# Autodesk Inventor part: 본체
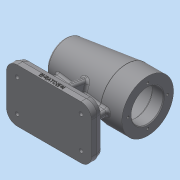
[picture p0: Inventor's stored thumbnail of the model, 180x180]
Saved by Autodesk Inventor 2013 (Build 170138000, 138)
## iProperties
Created: 2017-01
Part Number: 본체
Material: 일반
Document SubType Name: Modeling
Designer: dgall
Density: 1 g/cm^3
Author: dgall
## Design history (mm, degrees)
sketch "스케치1"
  geometry: L1 (-56, 0)-(56, 0); L2 (-52.27, 24.144)-(28, 34); L3 (28, 34)-(56, 34); L4 (56, 34)-(56, 0); L5 (-56, -60)-(56, -60); L6 (56, -60)-(56, -67); L7 (56, -67)-(-56, -67); L8 (-56, -67)-(-56, -60); L9 (-50, 0)-(-50, 10.5); L10 (-50, 10.5)-(-47, 10.5); L11 (-47, 10.5)-(-47, 16); L12 (-47, 16)-(-43, 16); L13 (-43, 16)-(-43, 17.5); L14 (-43, 17.5)-(-25, 17.5); L15 (-25, 17.5)-(-25, 21); L16 (-25, 21)-(-13, 21); L17 (-13, 21)-(-13, 24); L18 (-13, 24)-(41, 24); L19 (41, 24)-(41, 21); L20 (41, 21)-(56, 21); A1 r 80 centre (24, 0) between (-52.27, 24.144) and (-56, 0); 3 further points
  constraints: 40 end point, 14 parallel, 3 midpoint, 3 perpendicular, 2 horizontal, 2 point on circle, 2 point on line, 1 centre point, 1 coincident, 1 horizontal alignment, 1 vertical alignment
  dimensions: "d0" = 112 distance of L1.start L1.end; "d2" = 28 distance of L2.end L3.end; "d3" = 7 deg angle of L2 L3; "d4" = 80 radius of A1; "d5" = 68 diameter of L3 L1; "d6" = 7 distance of L5.end L6.end; "d7" = 67 distance from line of L1.start L7; "d8" = 112 distance of L6.end L7.end; "d9" = 15 distance of L19.end L20.end; "d10" = 54 distance of L17.end L18.end; "d11" = 12 distance of L15.end L16.end; "d12" = 18 distance of L13.end L14.end; "d13" = 4 distance of L11.end L12.end; "d14" = 3 distance of L9.end L10.end; "d15" = 21 diameter of L10 L1; "d16" = 32 diameter of L12 L1; "d17" = 35 diameter of L14 L1; "d18" = 42 diameter of L16 L1; "d19" = 48 diameter of L18 L1; "d20" = 42 diameter of L20 L1
revolve "회전1" stored, may be unused: angle "d21" = 90 deg
extrude "돌출1" join sketch "스케치1" stored distance "d22" = 70; taper "d23" = 0 deg
feature "면 기울기1" dims angle "d24" = -15 deg
fillet "모깎기1" dims "d44" = 14
sketch "스케치2"
  geometry: L1 (112, 0)-(112, -70) reference; L2 (0, 0)-(112, 0) reference; L3 (0, 0)-(0, -70) reference; L4 (112, -70)-(0, -70) reference; 1 further point
extrude "돌출2" join sketch "스케치2" distance "d25" = 7; taper "d26" = 0 deg
sketch "스케치3"
  geometry: L1 (0, 66.249)-(108.249, 66.249) reference; L2 (16.124, 37.124)-(50.124, 37.124); L3 (50.124, 37.124)-(50.124, 56.124); L4 (50.124, 56.124)-(58.124, 56.124); L5 (58.124, 56.124)-(58.124, 37.124); L6 (58.124, 37.124)-(92.124, 37.124); L7 (92.124, 37.124)-(92.124, 29.124); L8 (92.124, 29.124)-(58.124, 29.124); L9 (58.124, 29.124)-(58.124, 10.124); L10 (58.124, 10.124)-(50.124, 10.124); L11 (50.124, 10.124)-(50.124, 29.124); L12 (50.124, 29.124)-(16.124, 29.124); L13 (16.124, 29.124)-(16.124, 37.124); L14 (-1.876, 11.647)-(-1.876, 54.601) reference; L15 (96.601, 68.124)-(11.647, 68.124) reference; 6 further points
  constraints: 24 end point, 8 parallel, 3 equal length, 3 horizontal alignment, 3 vertical alignment, 2 collinear, 2 midpoint, 2 perpendicular
  dimensions: "d27" = 8 distance of L3.end L4.end; "d29" = 18 distance between parallel lines of L13 L14; "d30" = 12 distance between parallel lines of L4 L15
extrude "돌출3" join sketch "스케치3" stored distance "d31" = 7; taper "d32" = 0 deg
sketch "스케치4"
  geometry: C1 r 21 at (0, 0) reference; 1 further point
  constraints: 1 vertical alignment
  dimensions: "d33" = 26 distance of point (0, 26) C1.centre
hole "구멍1" sketch "스케치4" at (0, 26) diameter "d34" = 3.242; stored, may be unused: countersink angle "d38" = 90 deg, drill point angle "d40" = 118 deg; dims "d35" = 8, "d36" = 4, "d37" = 2, "d39" = 11
fillet "모깎기2" dims "d45" = 14
sketch "스케치7"
  geometry: L1 (4.375, 54.124)-(1.488, 49.124); L2 (1.488, 49.124)-(-4.285, 49.124); L3 (-4.285, 49.124)-(-7.172, 54.124); L4 (-7.172, 54.124)-(-4.285, 59.124); L5 (-4.285, 59.124)-(1.488, 59.124); L6 (1.488, 59.124)-(4.375, 54.124); L7 (-15.399, 12.124)-(-15.399, 54.124) reference; L8 (82.601, 68.124)-(-1.399, 68.124) reference; C1 r 5 at (-1.399, 54.124); 7 further points; 1 other entity
  constraints: 12 end point, 3 coincident, 1 centre point, 1 horizontal alignment, 1 tangent, 14 other
  dimensions: "d70" = 14 distance from line of point (-1.399, 54.124) L7; "d71" = 10 diameter of C1; "d72" = 14 distance from line of C1.centre L8 (= d70)
extrude "돌출4" cut sketch "스케치7" distance "d73" = 4; taper "d74" = 0 deg
sketch "스케치8"
  geometry: L1 (-15.399, 12.124)-(-15.399, 54.124) reference; L2 (82.601, 68.124)-(-1.399, 68.124) reference; 2 further points
  dimensions: "d81" = 14 distance from line of point (-1.399, 54.124) L1; "d82" = 14 distance from line of point (-1.399, 54.124) L2
hole "구멍3" sketch "스케치8" at (-1.399, 54.124) diameter "d83" = 5; stored, may be unused: countersink angle "d87" = 90 deg, drill point angle "d89" = 118 deg; dims "d84" = 8, "d85" = 10, "d86" = 4, "d88" = 11
feature "면 기울기2" dims angle "d53" = 10 deg
chamfer "모따기1" distance "d54" = 1; stored, may be unused: second distance "d55" = 2, angle "d56" = 45 deg
fillet "모깎기3" dims "d57" = 0.3, "d58" = 3
fillet "모깎기4" dims "d59" = 3
fillet "모깎기5" dims "d60" = 3
fillet "모깎기6" dims "d61" = 3
fillet "모깎기7" dims "d62" = 1
node "작업 평면1"
sketch "스케치6"
  geometry: L1 (56, -74)-(42, -74) reference; 2 further points
  constraints: 1 vertical alignment, 1 other
  dimensions: "d64" = 4 distance from line of point (0, -70) L1
feature "엠보싱1" sketch "스케치6" dims "d0" = 112, "d2" = 28, "d3" = 7 deg, "d4" = 80, "d5" = 68, "d6" = 7, "d7" = 67, "d8" = 112, "d9" = 15, "d10" = 54, "d11" = 12, "d12" = 18, "d13" = 4, "d14" = 3, "d15" = 21, "d16" = 32, "d17" = 35, "d18" = 42, "d19" = 48, "d20" = 42, "d65" = 0.5, "d66" = 0
node "솔리드1"
pattern_circular "원형 패턴1" dims angle "d42" = 360 deg
pattern_linear "직사각형 패턴1" dims "d77" = 42, "d80" = 84
pattern_linear "직사각형 패턴2" dims "d92" = 42, "d95" = 84
